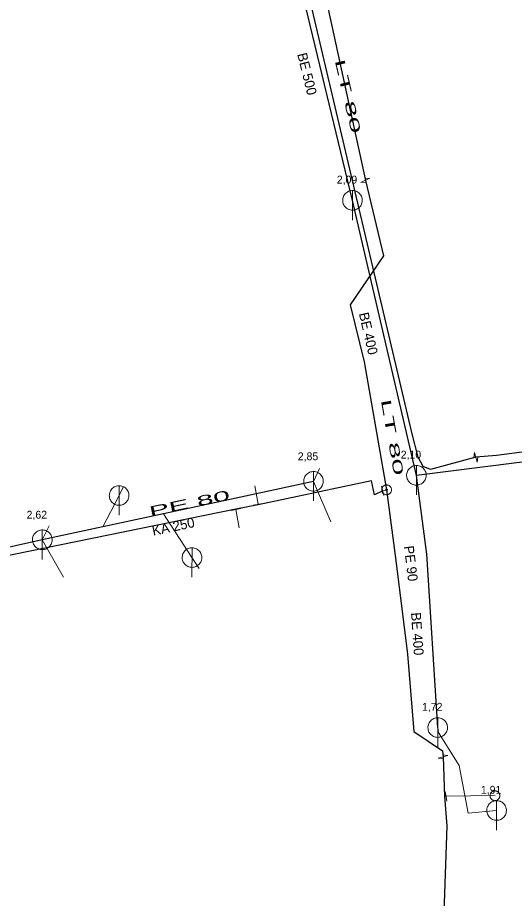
# Model space of a CAD drawing. Extents: x -682839 to -682312, y -994645 to -993949.
# Drawn here: x -682705.1 to -682654.5, y -994308.3 to -994218.6 of the extents above; entities that cross this region are included whole.
import ezdxf

# ---------------------------------------------------------------- set-up
doc = ezdxf.new("R2010")
doc.units = 0
doc.header["$LTSCALE"] = 0.4
doc.layers.add('1', color=7, linetype='Continuous')
for name, color, linetype, lineweight in [('11', 7, 'Continuous', 13), ('13', 7, 'Continuous', 13), ('14', 7, 'Continuous', 25), ('17', 7, 'Continuous', 25), ('22', 7, 'Continuous', 13), ('23', 7, 'Continuous', 13), ('34', 7, 'Continuous', 13), ('47', 7, 'Continuous', 13)]:
    doc.layers.add(name, color=color, linetype=linetype, lineweight=lineweight)

msp = doc.modelspace()

# ---------------------------------------------------------------- linework, layer by layer
at = {"layer": '11'}
for p, q in [((-682674.34, -994264.53), (-682674.94, -994265.829)), ((-682673.18, -994269.94), (-682674.94, -994265.829)), ((-682694.294, -994266.34), (-682694.744, -994267.27)), ((-682694.744, -994267.27), (-682696.399, -994270.449)), ((-682701.859, -994270.359), (-682702.57, -994271.78)), ((-682700.399, -994275.6), (-682702.57, -994271.78))]:
    msp.add_line(p, q, dxfattribs=at)
for points in [[(-682686.592, -994274.714), (-682687.318, -994273.591), (-682690.21, -994269.12)], [(-682656.28, -994299.359), (-682659.18, -994299.62), (-682660.09, -994294.76), (-682662.21, -994291.41), (-682662.28, -994290.91)]]:
    msp.add_lwpolyline(points, dxfattribs=at)
at = {"layer": '13'}
for p, q in [((-682680.588, -994268.16), (-682680.92, -994266.3)), ((-682682.85, -994268.699), (-682682.51, -994270.55)), ((-682661.439, -994297.909), (-682656.429, -994297.839))]:
    msp.add_line(p, q, dxfattribs=at)
at = {"layer": '14'}
for p, q in [((-682670.965, -994237.204), (-682676.98, -994212.32)), ((-682664.452, -994265.215), (-682670.965, -994237.204))]:
    msp.add_line(p, q, dxfattribs=at)
at = {"layer": '14', "lineweight": 13}
for p, q in [((-682667.489, -994266.691), (-682667.88, -994266.789)), ((-682680.579, -994268.21), (-682680.588, -994268.16)), ((-682682.859, -994268.649), (-682682.85, -994268.699)), ((-682661.579, -994297.93), (-682661.439, -994297.909))]:
    msp.add_line(p, q, dxfattribs=at)
at = {"layer": '14'}
for points in [[(-682621.469, -994260.079), (-682650.07, -994263.421), (-682650.991, -994263.524), (-682664.452, -994265.215)], [(-682674.94, -994265.829), (-682690.21, -994269.12), (-682696.399, -994270.449), (-682702.57, -994271.78)], [(-682662.28, -994290.91), (-682663.39, -994273.25), (-682664.452, -994265.215)], [(-682702.57, -994271.78), (-682711.829, -994273.859), (-682720.37, -994275.78), (-682738.739, -994279.899)]]:
    msp.add_lwpolyline(points, dxfattribs=at)
at = {"layer": '17'}
for points in [[(-682682.065, -994177.804), (-682676.664, -994202.874), (-682669.647, -994235.166)], [(-682658.389, -994263.379), (-682663.01, -994264.62), (-682663.77, -994264.3), (-682664.26, -994263.37), (-682664.93, -994260.84), (-682678.495, -994203.114), (-682682.079, -994187.859), (-682683.409, -994181.449)], [(-682669.647, -994235.166), (-682667.789, -994242.87), (-682671.19, -994247.859), (-682669.76, -994253.66), (-682667.489, -994266.691)], [(-682575, -994253.756), (-682585.09, -994254.838), (-682594.877, -994255.783), (-682595.977, -994255.888), (-682601.16, -994256.39), (-682606.69, -994257.25), (-682621.798, -994259.055), (-682622.134, -994259.092), (-682631.52, -994260.16), (-682642.26, -994261.399), (-682649.861, -994262.37), (-682651.096, -994262.526), (-682656.289, -994263.19), (-682658.389, -994263.379)], [(-682667.88, -994266.789), (-682668.739, -994267.21), (-682669.02, -994265.78), (-682680.579, -994268.21), (-682682.859, -994268.649), (-682708.84, -994273.969), (-682728.789, -994278.48), (-682741.8, -994281.719)], [(-682667.489, -994266.691), (-682666.535, -994273.899), (-682665.353, -994283.418), (-682664.706, -994291.318), (-682661.795, -994293.285), (-682661.734, -994293.879)], [(-682661.734, -994293.879), (-682661.579, -994297.93), (-682661.366, -994300.932), (-682663.509, -994363.011)]]:
    msp.add_lwpolyline(points, dxfattribs=at)
at = {"layer": '22'}
for p, q in [((-682670.965, -994239.204), (-682670.964, -994236.204)), ((-682674.94, -994267.829), (-682674.939, -994264.829)), ((-682664.452, -994267.216), (-682664.451, -994264.216)), ((-682694.744, -994269.27), (-682694.743, -994266.27)), ((-682702.57, -994273.78), (-682702.569, -994270.78)), ((-682687.318, -994275.591), (-682687.317, -994272.591)), ((-682662.28, -994292.91), (-682662.279, -994289.91)), ((-682656.28, -994301.359), (-682656.279, -994298.359))]:
    msp.add_line(p, q, dxfattribs=at)
for points in [[(-682669.965, -994237.204), (-682669.97, -994237.095), (-682669.988, -994236.987), (-682670.018, -994236.881), (-682670.058, -994236.78), (-682670.11, -994236.683), (-682670.172, -994236.593), (-682670.244, -994236.51), (-682670.324, -994236.436), (-682670.412, -994236.37), (-682670.506, -994236.315), (-682670.606, -994236.27), (-682670.711, -994236.237), (-682670.818, -994236.215), (-682670.927, -994236.205), (-682671.037, -994236.207), (-682671.145, -994236.221), (-682671.252, -994236.246), (-682671.355, -994236.283), (-682671.453, -994236.332), (-682671.545, -994236.39), (-682671.631, -994236.459), (-682671.708, -994236.536), (-682671.777, -994236.622), (-682671.836, -994236.714), (-682671.884, -994236.812), (-682671.921, -994236.915), (-682671.947, -994237.022), (-682671.961, -994237.13), (-682671.964, -994237.24), (-682671.954, -994237.349), (-682671.933, -994237.456), (-682671.899, -994237.56), (-682671.855, -994237.66), (-682671.8, -994237.755), (-682671.734, -994237.843), (-682671.66, -994237.923), (-682671.577, -994237.995), (-682671.487, -994238.057), (-682671.391, -994238.109), (-682671.289, -994238.15), (-682671.184, -994238.18), (-682671.076, -994238.198), (-682670.966, -994238.204), (-682670.857, -994238.198), (-682670.749, -994238.18), (-682670.644, -994238.151), (-682670.542, -994238.11), (-682670.445, -994238.058), (-682670.355, -994237.996), (-682670.272, -994237.925), (-682670.197, -994237.845), (-682670.132, -994237.757), (-682670.076, -994237.663), (-682670.032, -994237.563), (-682669.998, -994237.459), (-682669.976, -994237.351), (-682669.966, -994237.242)], [(-682673.94, -994265.829), (-682673.945, -994265.72), (-682673.963, -994265.612), (-682673.993, -994265.506), (-682674.033, -994265.405), (-682674.085, -994265.308), (-682674.147, -994265.218), (-682674.219, -994265.135), (-682674.299, -994265.061), (-682674.387, -994264.995), (-682674.481, -994264.94), (-682674.581, -994264.895), (-682674.686, -994264.862), (-682674.793, -994264.84), (-682674.902, -994264.83), (-682675.012, -994264.832), (-682675.12, -994264.846), (-682675.227, -994264.871), (-682675.33, -994264.908), (-682675.428, -994264.957), (-682675.52, -994265.015), (-682675.606, -994265.084), (-682675.683, -994265.161), (-682675.752, -994265.247), (-682675.811, -994265.339), (-682675.859, -994265.437), (-682675.896, -994265.54), (-682675.922, -994265.647), (-682675.936, -994265.755), (-682675.939, -994265.865), (-682675.929, -994265.974), (-682675.908, -994266.081), (-682675.874, -994266.185), (-682675.83, -994266.285), (-682675.775, -994266.38), (-682675.709, -994266.468), (-682675.635, -994266.548), (-682675.552, -994266.62), (-682675.462, -994266.682), (-682675.366, -994266.734), (-682675.264, -994266.775), (-682675.159, -994266.805), (-682675.051, -994266.823), (-682674.941, -994266.829), (-682674.832, -994266.823), (-682674.724, -994266.805), (-682674.619, -994266.776), (-682674.517, -994266.735), (-682674.42, -994266.683), (-682674.33, -994266.621), (-682674.247, -994266.55), (-682674.172, -994266.47), (-682674.107, -994266.382), (-682674.051, -994266.288), (-682674.007, -994266.188), (-682673.973, -994266.084), (-682673.951, -994265.976), (-682673.941, -994265.867)], [(-682663.452, -994265.216), (-682663.457, -994265.107), (-682663.475, -994264.999), (-682663.505, -994264.893), (-682663.545, -994264.792), (-682663.597, -994264.695), (-682663.659, -994264.605), (-682663.731, -994264.522), (-682663.811, -994264.448), (-682663.899, -994264.382), (-682663.993, -994264.327), (-682664.093, -994264.282), (-682664.198, -994264.249), (-682664.305, -994264.227), (-682664.414, -994264.217), (-682664.524, -994264.219), (-682664.632, -994264.233), (-682664.739, -994264.258), (-682664.842, -994264.295), (-682664.94, -994264.344), (-682665.032, -994264.402), (-682665.118, -994264.471), (-682665.195, -994264.548), (-682665.264, -994264.634), (-682665.323, -994264.726), (-682665.371, -994264.824), (-682665.408, -994264.927), (-682665.434, -994265.034), (-682665.448, -994265.142), (-682665.451, -994265.252), (-682665.441, -994265.361), (-682665.42, -994265.468), (-682665.386, -994265.572), (-682665.342, -994265.672), (-682665.287, -994265.767), (-682665.221, -994265.855), (-682665.147, -994265.935), (-682665.064, -994266.007), (-682664.974, -994266.069), (-682664.878, -994266.121), (-682664.776, -994266.162), (-682664.671, -994266.192), (-682664.563, -994266.21), (-682664.453, -994266.216), (-682664.344, -994266.21), (-682664.236, -994266.192), (-682664.131, -994266.163), (-682664.029, -994266.122), (-682663.932, -994266.07), (-682663.842, -994266.008), (-682663.759, -994265.937), (-682663.684, -994265.857), (-682663.619, -994265.769), (-682663.563, -994265.675), (-682663.519, -994265.575), (-682663.485, -994265.471), (-682663.463, -994265.363), (-682663.453, -994265.254)], [(-682693.744, -994267.27), (-682693.749, -994267.161), (-682693.767, -994267.053), (-682693.797, -994266.947), (-682693.837, -994266.846), (-682693.889, -994266.749), (-682693.951, -994266.659), (-682694.023, -994266.576), (-682694.103, -994266.502), (-682694.191, -994266.436), (-682694.285, -994266.381), (-682694.385, -994266.336), (-682694.49, -994266.303), (-682694.597, -994266.281), (-682694.706, -994266.271), (-682694.816, -994266.273), (-682694.924, -994266.287), (-682695.031, -994266.312), (-682695.134, -994266.349), (-682695.232, -994266.398), (-682695.324, -994266.456), (-682695.41, -994266.525), (-682695.487, -994266.602), (-682695.556, -994266.688), (-682695.615, -994266.78), (-682695.663, -994266.878), (-682695.7, -994266.981), (-682695.726, -994267.088), (-682695.74, -994267.196), (-682695.743, -994267.306), (-682695.733, -994267.415), (-682695.712, -994267.522), (-682695.678, -994267.626), (-682695.634, -994267.726), (-682695.579, -994267.821), (-682695.513, -994267.909), (-682695.439, -994267.989), (-682695.356, -994268.061), (-682695.266, -994268.123), (-682695.17, -994268.175), (-682695.068, -994268.216), (-682694.963, -994268.246), (-682694.855, -994268.264), (-682694.745, -994268.27), (-682694.636, -994268.264), (-682694.528, -994268.246), (-682694.423, -994268.217), (-682694.321, -994268.176), (-682694.224, -994268.124), (-682694.134, -994268.062), (-682694.051, -994267.991), (-682693.976, -994267.911), (-682693.911, -994267.823), (-682693.855, -994267.729), (-682693.811, -994267.629), (-682693.777, -994267.525), (-682693.755, -994267.417), (-682693.745, -994267.308)], [(-682701.57, -994271.78), (-682701.575, -994271.671), (-682701.593, -994271.563), (-682701.623, -994271.457), (-682701.663, -994271.356), (-682701.715, -994271.259), (-682701.777, -994271.169), (-682701.849, -994271.086), (-682701.929, -994271.012), (-682702.017, -994270.946), (-682702.111, -994270.891), (-682702.211, -994270.846), (-682702.316, -994270.813), (-682702.423, -994270.791), (-682702.532, -994270.781), (-682702.642, -994270.783), (-682702.75, -994270.797), (-682702.857, -994270.822), (-682702.96, -994270.859), (-682703.058, -994270.908), (-682703.15, -994270.966), (-682703.236, -994271.035), (-682703.313, -994271.112), (-682703.382, -994271.198), (-682703.441, -994271.29), (-682703.489, -994271.388), (-682703.526, -994271.491), (-682703.552, -994271.598), (-682703.566, -994271.706), (-682703.569, -994271.816), (-682703.559, -994271.925), (-682703.538, -994272.032), (-682703.504, -994272.136), (-682703.46, -994272.236), (-682703.405, -994272.331), (-682703.339, -994272.419), (-682703.265, -994272.499), (-682703.182, -994272.571), (-682703.092, -994272.633), (-682702.996, -994272.685), (-682702.894, -994272.726), (-682702.789, -994272.756), (-682702.681, -994272.774), (-682702.571, -994272.78), (-682702.462, -994272.774), (-682702.354, -994272.756), (-682702.249, -994272.727), (-682702.147, -994272.686), (-682702.05, -994272.634), (-682701.96, -994272.572), (-682701.877, -994272.501), (-682701.802, -994272.421), (-682701.737, -994272.333), (-682701.681, -994272.239), (-682701.637, -994272.139), (-682701.603, -994272.035), (-682701.581, -994271.927), (-682701.571, -994271.818)], [(-682686.318, -994273.591), (-682686.323, -994273.482), (-682686.341, -994273.374), (-682686.371, -994273.268), (-682686.411, -994273.167), (-682686.463, -994273.07), (-682686.525, -994272.98), (-682686.597, -994272.897), (-682686.677, -994272.823), (-682686.765, -994272.757), (-682686.859, -994272.702), (-682686.959, -994272.657), (-682687.064, -994272.624), (-682687.171, -994272.602), (-682687.28, -994272.592), (-682687.39, -994272.594), (-682687.498, -994272.608), (-682687.605, -994272.633), (-682687.708, -994272.67), (-682687.806, -994272.719), (-682687.898, -994272.777), (-682687.984, -994272.846), (-682688.061, -994272.923), (-682688.13, -994273.009), (-682688.189, -994273.101), (-682688.237, -994273.199), (-682688.274, -994273.302), (-682688.3, -994273.409), (-682688.314, -994273.517), (-682688.317, -994273.627), (-682688.307, -994273.736), (-682688.286, -994273.843), (-682688.252, -994273.947), (-682688.208, -994274.047), (-682688.153, -994274.142), (-682688.087, -994274.23), (-682688.013, -994274.31), (-682687.93, -994274.382), (-682687.84, -994274.444), (-682687.744, -994274.496), (-682687.642, -994274.537), (-682687.537, -994274.567), (-682687.429, -994274.585), (-682687.319, -994274.591), (-682687.21, -994274.585), (-682687.102, -994274.567), (-682686.997, -994274.538), (-682686.895, -994274.497), (-682686.798, -994274.445), (-682686.708, -994274.383), (-682686.625, -994274.312), (-682686.55, -994274.232), (-682686.485, -994274.144), (-682686.429, -994274.05), (-682686.385, -994273.95), (-682686.351, -994273.846), (-682686.329, -994273.738), (-682686.319, -994273.629)], [(-682661.28, -994290.91), (-682661.285, -994290.801), (-682661.303, -994290.693), (-682661.333, -994290.587), (-682661.373, -994290.486), (-682661.425, -994290.389), (-682661.487, -994290.299), (-682661.559, -994290.216), (-682661.639, -994290.142), (-682661.727, -994290.076), (-682661.821, -994290.021), (-682661.921, -994289.976), (-682662.026, -994289.943), (-682662.133, -994289.921), (-682662.242, -994289.911), (-682662.352, -994289.913), (-682662.46, -994289.927), (-682662.567, -994289.952), (-682662.67, -994289.989), (-682662.768, -994290.038), (-682662.86, -994290.096), (-682662.946, -994290.165), (-682663.023, -994290.242), (-682663.092, -994290.328), (-682663.151, -994290.42), (-682663.199, -994290.518), (-682663.236, -994290.621), (-682663.262, -994290.728), (-682663.276, -994290.836), (-682663.279, -994290.946), (-682663.269, -994291.055), (-682663.248, -994291.162), (-682663.214, -994291.266), (-682663.17, -994291.366), (-682663.115, -994291.461), (-682663.049, -994291.549), (-682662.975, -994291.629), (-682662.892, -994291.701), (-682662.802, -994291.763), (-682662.706, -994291.815), (-682662.604, -994291.856), (-682662.499, -994291.886), (-682662.391, -994291.904), (-682662.281, -994291.91), (-682662.172, -994291.904), (-682662.064, -994291.886), (-682661.959, -994291.857), (-682661.857, -994291.816), (-682661.76, -994291.764), (-682661.67, -994291.702), (-682661.587, -994291.631), (-682661.512, -994291.551), (-682661.447, -994291.463), (-682661.391, -994291.369), (-682661.347, -994291.269), (-682661.313, -994291.165), (-682661.291, -994291.057), (-682661.281, -994290.948)], [(-682655.28, -994299.359), (-682655.285, -994299.25), (-682655.303, -994299.142), (-682655.333, -994299.036), (-682655.373, -994298.935), (-682655.425, -994298.838), (-682655.487, -994298.748), (-682655.559, -994298.665), (-682655.639, -994298.591), (-682655.727, -994298.525), (-682655.821, -994298.47), (-682655.921, -994298.425), (-682656.026, -994298.392), (-682656.133, -994298.37), (-682656.242, -994298.36), (-682656.352, -994298.362), (-682656.46, -994298.376), (-682656.567, -994298.401), (-682656.67, -994298.438), (-682656.768, -994298.487), (-682656.86, -994298.545), (-682656.946, -994298.614), (-682657.023, -994298.691), (-682657.092, -994298.777), (-682657.151, -994298.869), (-682657.199, -994298.967), (-682657.236, -994299.07), (-682657.262, -994299.177), (-682657.276, -994299.285), (-682657.279, -994299.395), (-682657.269, -994299.504), (-682657.248, -994299.611), (-682657.214, -994299.715), (-682657.17, -994299.815), (-682657.115, -994299.91), (-682657.049, -994299.998), (-682656.975, -994300.078), (-682656.892, -994300.15), (-682656.802, -994300.212), (-682656.706, -994300.264), (-682656.604, -994300.305), (-682656.499, -994300.335), (-682656.391, -994300.353), (-682656.281, -994300.359), (-682656.172, -994300.353), (-682656.064, -994300.335), (-682655.959, -994300.306), (-682655.857, -994300.265), (-682655.76, -994300.213), (-682655.67, -994300.151), (-682655.587, -994300.08), (-682655.512, -994300), (-682655.447, -994299.912), (-682655.391, -994299.818), (-682655.347, -994299.718), (-682655.313, -994299.614), (-682655.291, -994299.506), (-682655.281, -994299.397)]]:
    msp.add_lwpolyline(points, close=True, dxfattribs=at)
at = {"layer": '23'}
for points in [[(-682655.951, -994297.849), (-682655.955, -994297.796), (-682655.965, -994297.745), (-682655.98, -994297.696), (-682656, -994297.647), (-682656.025, -994297.601), (-682656.055, -994297.558), (-682656.089, -994297.518), (-682656.126, -994297.483), (-682656.168, -994297.45), (-682656.212, -994297.423), (-682656.26, -994297.4), (-682656.31, -994297.382), (-682656.36, -994297.37), (-682656.411, -994297.364), (-682656.463, -994297.361), (-682656.517, -994297.366), (-682656.567, -994297.375), (-682656.619, -994297.391), (-682656.666, -994297.409), (-682656.712, -994297.434), (-682656.756, -994297.466), (-682656.795, -994297.499), (-682656.832, -994297.538), (-682656.864, -994297.578), (-682656.891, -994297.622), (-682656.913, -994297.671), (-682656.93, -994297.719), (-682656.943, -994297.77), (-682656.949, -994297.822), (-682656.951, -994297.874), (-682656.947, -994297.926), (-682656.938, -994297.978), (-682656.923, -994298.029), (-682656.903, -994298.077), (-682656.878, -994298.121), (-682656.848, -994298.165), (-682656.814, -994298.205), (-682656.776, -994298.242), (-682656.734, -994298.273)], [(-682656.619, -994297.391), (-682656.666, -994297.409), (-682656.712, -994297.434), (-682656.756, -994297.466), (-682656.795, -994297.499), (-682656.832, -994297.538), (-682656.864, -994297.578), (-682656.891, -994297.622), (-682656.913, -994297.671), (-682656.93, -994297.719), (-682656.943, -994297.77), (-682656.949, -994297.822), (-682656.951, -994297.874), (-682656.947, -994297.926), (-682656.938, -994297.978), (-682656.923, -994298.029), (-682656.903, -994298.077), (-682656.878, -994298.121), (-682656.848, -994298.165), (-682656.814, -994298.205), (-682656.776, -994298.242), (-682656.734, -994298.273), (-682656.691, -994298.301), (-682656.643, -994298.323), (-682656.594, -994298.341), (-682656.542, -994298.353), (-682656.491, -994298.359), (-682656.439, -994298.361), (-682656.387, -994298.356), (-682656.335, -994298.348), (-682656.285, -994298.333), (-682656.237, -994298.312), (-682656.19, -994298.288), (-682656.148, -994298.259), (-682656.108, -994298.224), (-682656.072, -994298.187), (-682656.04, -994298.146), (-682656.012, -994298.1), (-682655.989, -994298.053), (-682655.972, -994298.004)], [(-682656.734, -994298.273), (-682656.691, -994298.301), (-682656.643, -994298.323), (-682656.594, -994298.341), (-682656.542, -994298.353), (-682656.491, -994298.359), (-682656.439, -994298.361), (-682656.387, -994298.356), (-682656.335, -994298.348), (-682656.285, -994298.333), (-682656.237, -994298.312), (-682656.19, -994298.288), (-682656.148, -994298.259), (-682656.108, -994298.224), (-682656.072, -994298.187), (-682656.04, -994298.146), (-682656.012, -994298.1), (-682655.989, -994298.053), (-682655.972, -994298.004), (-682655.961, -994297.952), (-682655.954, -994297.901), (-682655.951, -994297.849), (-682655.955, -994297.796), (-682655.965, -994297.745), (-682655.98, -994297.696), (-682656, -994297.647), (-682656.025, -994297.601), (-682656.055, -994297.558), (-682656.089, -994297.518), (-682656.126, -994297.483), (-682656.168, -994297.45), (-682656.212, -994297.423), (-682656.26, -994297.4), (-682656.31, -994297.382), (-682656.36, -994297.37), (-682656.411, -994297.364), (-682656.463, -994297.361), (-682656.517, -994297.366), (-682656.567, -994297.375), (-682656.619, -994297.391)], [(-682655.972, -994298.004), (-682655.961, -994297.952), (-682655.954, -994297.901), (-682655.951, -994297.849)]]:
    msp.add_lwpolyline(points, dxfattribs=at)
at = {"layer": '34'}
for p, q in [((-682668.003, -994266.304), (-682667.757, -994267.273)), ((-682681.08, -994268.248), (-682680.095, -994268.072)), ((-682682.358, -994268.607), (-682683.341, -994268.789)), ((-682661.51, -994297.414), (-682661.368, -994298.404))]:
    msp.add_line(p, q, dxfattribs=at)
at = {"layer": '47'}
for p, q in [((-682669.183, -994234.953), (-682669.694, -994234.97)), ((-682658.531, -994262.889), (-682658.589, -994263.397)), ((-682661.242, -994293.745), (-682661.748, -994293.678))]:
    msp.add_line(p, q, dxfattribs=at)
for points in [[(-682669.183, -994234.953), (-682670.11, -994235.378), (-682669.599, -994235.361)], [(-682658.531, -994262.889), (-682658.246, -994263.868), (-682658.188, -994263.36)], [(-682661.242, -994293.745), (-682662.225, -994294.012), (-682661.719, -994294.079)]]:
    msp.add_lwpolyline(points, dxfattribs=at)
for points in [[(-682666.99, -994266.691), (-682666.993, -994266.639), (-682667.001, -994266.587), (-682667.015, -994266.537), (-682667.032, -994266.488), (-682667.057, -994266.441), (-682667.086, -994266.397), (-682667.119, -994266.357), (-682667.156, -994266.32), (-682667.196, -994266.287), (-682667.24, -994266.258), (-682667.287, -994266.233), (-682667.336, -994266.216), (-682667.386, -994266.202), (-682667.438, -994266.194), (-682667.49, -994266.191), (-682667.542, -994266.194), (-682667.594, -994266.202), (-682667.645, -994266.216), (-682667.693, -994266.233), (-682667.74, -994266.258), (-682667.784, -994266.287), (-682667.825, -994266.32), (-682667.862, -994266.357), (-682667.895, -994266.397), (-682667.923, -994266.441), (-682667.947, -994266.488), (-682667.966, -994266.537), (-682667.978, -994266.587), (-682667.987, -994266.639), (-682667.99, -994266.691), (-682667.987, -994266.743), (-682667.978, -994266.795), (-682667.966, -994266.846), (-682667.947, -994266.894), (-682667.923, -994266.941), (-682667.895, -994266.985), (-682667.862, -994267.026), (-682667.825, -994267.063), (-682667.784, -994267.096), (-682667.74, -994267.124), (-682667.693, -994267.148), (-682667.645, -994267.167), (-682667.594, -994267.179), (-682667.542, -994267.188), (-682667.49, -994267.191), (-682667.438, -994267.188), (-682667.386, -994267.179), (-682667.336, -994267.167), (-682667.287, -994267.148), (-682667.24, -994267.124), (-682667.196, -994267.096), (-682667.156, -994267.063), (-682667.119, -994267.026), (-682667.086, -994266.985), (-682667.057, -994266.941), (-682667.032, -994266.894), (-682667.015, -994266.846), (-682667.001, -994266.795), (-682666.993, -994266.743)], [(-682667.407, -994266.691), (-682667.407, -994266.682), (-682667.41, -994266.674), (-682667.412, -994266.666), (-682667.415, -994266.657), (-682667.419, -994266.65), (-682667.424, -994266.643), (-682667.429, -994266.636), (-682667.434, -994266.63), (-682667.442, -994266.625), (-682667.449, -994266.62), (-682667.456, -994266.616), (-682667.465, -994266.613), (-682667.473, -994266.611), (-682667.481, -994266.608), (-682667.49, -994266.608), (-682667.499, -994266.608), (-682667.507, -994266.611), (-682667.515, -994266.613), (-682667.523, -994266.616), (-682667.531, -994266.62), (-682667.538, -994266.625), (-682667.545, -994266.63), (-682667.551, -994266.636), (-682667.557, -994266.643), (-682667.561, -994266.65), (-682667.565, -994266.657), (-682667.568, -994266.666), (-682667.57, -994266.674), (-682667.572, -994266.682), (-682667.572, -994266.691), (-682667.572, -994266.7), (-682667.57, -994266.708), (-682667.568, -994266.716), (-682667.565, -994266.724), (-682667.561, -994266.732), (-682667.557, -994266.739), (-682667.551, -994266.746), (-682667.545, -994266.752), (-682667.538, -994266.758), (-682667.531, -994266.762), (-682667.523, -994266.766), (-682667.515, -994266.769), (-682667.507, -994266.771), (-682667.499, -994266.773), (-682667.49, -994266.773), (-682667.481, -994266.773), (-682667.473, -994266.771), (-682667.465, -994266.769), (-682667.456, -994266.766), (-682667.449, -994266.762), (-682667.442, -994266.758), (-682667.434, -994266.752), (-682667.429, -994266.746), (-682667.424, -994266.739), (-682667.419, -994266.732), (-682667.415, -994266.724), (-682667.412, -994266.716), (-682667.41, -994266.708), (-682667.407, -994266.7)]]:
    msp.add_lwpolyline(points, close=True, dxfattribs=at)

# ---------------------------------------------------------------- texts
at = {"layer": '1'}
for s, rotation, p in [('BE 500', 284, (-682676.606, -994222.311)), ('BE 400', 283, (-682670.321, -994248.737)), ('KA 250', 12, (-682691.268, -994271.378)), ('PE 90 ', 277, (-682665.727, -994272.445)), ('BE 400', 274, (-682665.004, -994279.21))]:
    msp.add_text(s, height=1, rotation=rotation, dxfattribs=at).set_placement(p)
for s, rotation, width, p in [('LT 80 ', 283, 2.25, (-682672.784, -994222.954)), ('LT 80 ', 280, 2.3, (-682668.082, -994257.542)), ('PE 80 ', 12, 2.3, (-682691.576, -994269.413))]:
    msp.add_text(s, height=1, rotation=rotation, dxfattribs=dict(at, width=width)).set_placement(p)
for s, p in [('2,09', (-682672.564, -994235.492)), ('2,85', (-682676.539, -994263.677)), ('2,10', (-682666.051, -994263.504)), ('2,62', (-682704.17, -994269.627)), ('1,72', (-682663.88, -994289.198)), ('1,91', (-682657.88, -994297.648))]:
    msp.add_text(s, height=0.8, dxfattribs=at).set_placement(p)

doc.saveas('drawing.dxf')
